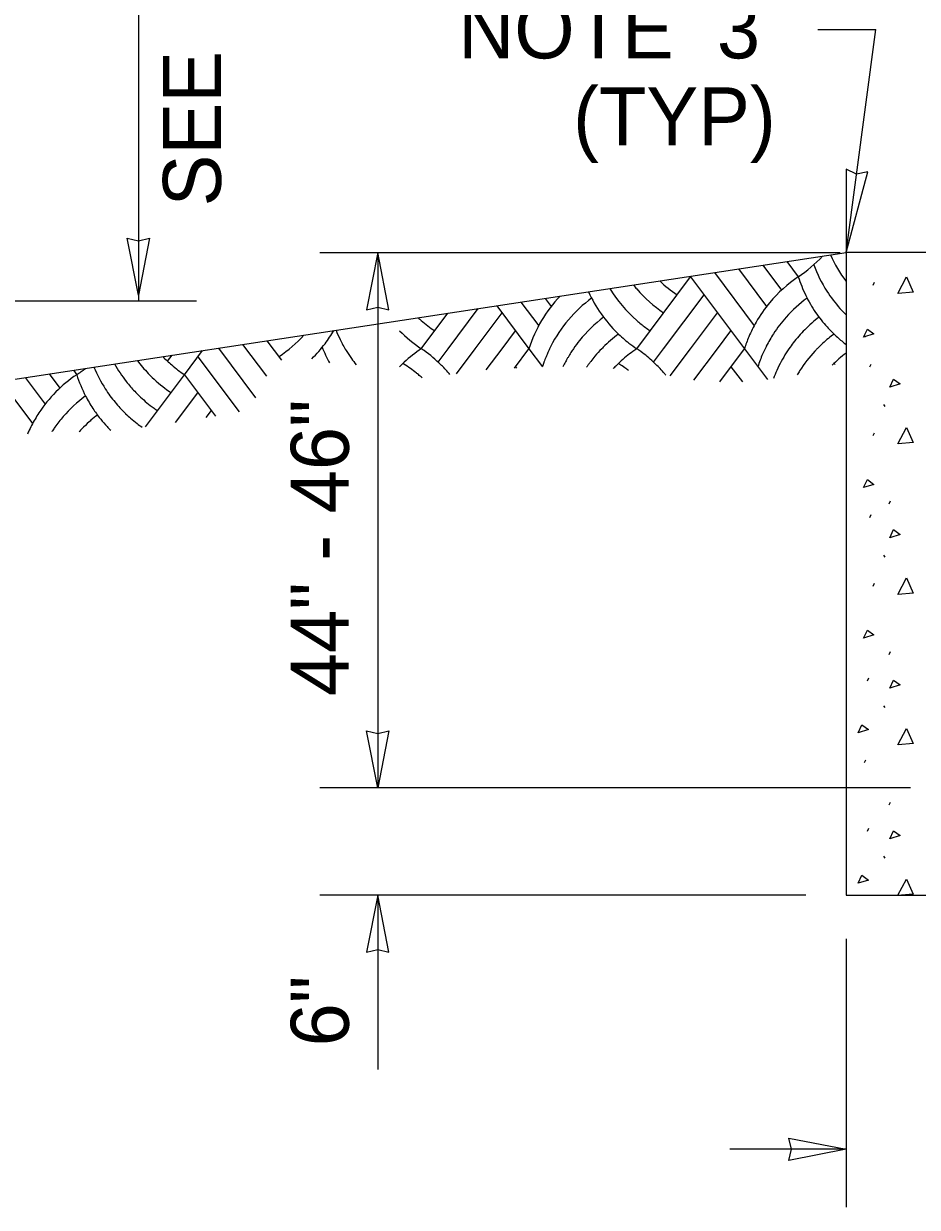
# Model space of a CAD drawing. Extents: x 99862 to 103151, y 99997 to 117076.
# Drawn here: x 101256 to 101502.3, y 109770.1 to 110096.3 of the extents above; entities that cross this region are included whole.
import ezdxf

# ---------------------------------------------------------------- set-up
doc = ezdxf.new("R2010")
doc.units = 0
for name, color, linetype in [('Level 15', 7, 'Continuous'), ('Level 20', 7, 'Continuous'), ('Level 5', 7, 'Continuous'), ('Level 6', 7, 'Continuous')]:
    doc.layers.add(name, color=color, linetype=linetype)

msp = doc.modelspace()

# ---------------------------------------------------------------- linework, layer by layer
at = {"layer": 'Level 15'}
for p, q in [((101287.59, 110394.09), (101287.59, 110019.86)), ((101474.86, 110094.68), (101490.86, 110094.68)), ((101482.66, 110033.17), (101490.86, 110094.68)), ((101353.59, 110033.16), (101353.59, 109885.66)), ((100971.29, 110019.86), (101303.59, 110019.86)), ((101500.42, 109885.66), (101337.59, 109885.66)), ((101471.56, 109856.1), (101337.59, 109856.1)), ((101353.59, 109856.1), (101353.59, 109808.1)), ((101482.66, 109844.1), (101482.66, 109770.1)), ((101482.66, 109786.1), (101450.66, 109786.1))]:
    msp.add_line(p, q, dxfattribs=at)
for points in [[(101482.66, 110033.17), (101488.64, 110055.41), (101485.54, 110054.75), (101482.72, 110056.2)], [(101287.6, 110021.44), (101284.51, 110037.16), (101287.6, 110036.43), (101290.68, 110037.16)], [(101353.59, 110033.16), (101350.5, 110017.44), (101353.59, 110018.17), (101356.67, 110017.44)], [(101353.59, 109885.66), (101350.5, 109901.39), (101353.59, 109900.66), (101356.67, 109901.39)], [(101353.59, 109856.1), (101350.5, 109840.37), (101353.59, 109841.1), (101356.67, 109840.37)], [(101482.66, 109786.1), (101466.93, 109783.01), (101467.66, 109786.1), (101466.93, 109789.18)]]:
    msp.add_lwpolyline(points, close=True, dxfattribs=at)
at = {"layer": 'Level 5'}
for p, q in [((101186.99, 109988.19), (101482.66, 110033.17)), ((101453.02, 110028.66), (101460.77, 110018.33)), ((101459.68, 110029.68), (101464.85, 110022.79)), ((101466.35, 110030.69), (101469.5, 110026.48)), ((101424.95, 110006.68), (101439.8, 110026.48)), ((101439.8, 110026.48), (101439.94, 110026.67)), ((101439.8, 110026.48), (101454.65, 110006.68)), ((101446.35, 110027.65), (101457.33, 110013.02)), ((101432.38, 110006.68), (101443.51, 110021.53)), ((101386.38, 110018.52), (101395.26, 110006.68)), ((101393.04, 110019.54), (101397.93, 110013.02)), ((101399.7, 110020.55), (101401.37, 110018.33)), ((101365.56, 110006.68), (101372.9, 110016.47)), ((101372.98, 110006.68), (101381.28, 110017.75)), ((101380.41, 110006.68), (101387.83, 110016.58)), ((101439.8, 110006.68), (101447.23, 110016.58)), ((101322.98, 110008.88), (101327.02, 110003.5)), ((101387.83, 110006.68), (101391.54, 110011.63)), ((101447.23, 110006.68), (101450.94, 110011.63)), ((101488.05, 110010.06), (101488.07, 110010.08)), ((101300.3, 109999.52), (101305.3, 110006.19)), ((101309.65, 110006.85), (101319.9, 109993.19)), ((101316.32, 110007.87), (101322.87, 109999.13)), ((101370.21, 110002.99), (101372.98, 110006.68)), ((101375.25, 109999.81), (101380.41, 110006.68)), ((101383.45, 110000.84), (101387.83, 110006.68)), ((101391.22, 110001.3), (101395.26, 110006.68)), ((101395.26, 110006.68), (101398.96, 110001.74)), ((101429.61, 110002.99), (101432.38, 110006.68)), ((101434.17, 109999.18), (101439.8, 110006.68)), ((101440.71, 109997.99), (101447.23, 110006.68)), ((101447.84, 109997.6), (101454.65, 110006.68)), ((101454.65, 110006.68), (101460.98, 109998.24)), ((101295.65, 110003.22), (101296.92, 110004.91)), ((101304.01, 110004.47), (101315.38, 109989.32)), ((101256.34, 109998.74), (101261.87, 109991.37)), ((101263.01, 109999.76), (101265.95, 109995.83)), ((101269.67, 110000.77), (101270.6, 109999.52)), ((101289.55, 109985.19), (101300.3, 109999.52)), ((101300.3, 109999.52), (101308.86, 109988.11)), ((101391.54, 110001.73), (101391.84, 110001.34)), ((101450.94, 110001.73), (101454.08, 109997.55)), ((101249.68, 109997.73), (101258.43, 109986.06)), ((101297.82, 109986.32), (101304.01, 109994.57)), ((101306.27, 109987.69), (101307.73, 109989.62))]:
    msp.add_line(p, q, dxfattribs=at)
msp.add_lwpolyline([(101337.59, 110033.16), (101481.02, 110033.16)], dxfattribs=at)
for centre, start, end in [((101448.54, 110057.67), 303.9036, 317.2843), ((101512.73, 110047.77), 203.9439, 216.8537), ((101509.02, 110042.82), 200.2432, 212.6697), ((101457.05, 110052.72), 226.7377, 236.0964), ((101460.76, 110057.67), 235.7238, 236.0964), ((101490.46, 109995.3), 123.9036, 140.1077), ((101505.31, 110037.87), 197.6434, 206.045), ((101445.91, 110037.87), 204.3601, 225.6138), ((101449.63, 110042.82), 211.3642, 228.9599), ((101453.34, 110047.77), 218.7492, 220.9416), ((101453.34, 110047.77), 220.9415, 236.0964), ((101509.02, 110042.82), 212.6697, 221.7589), ((101431.07, 109995.3), 136.4665, 162.3566), ((101434.78, 109990.35), 126.3063, 153.0821), ((101490.46, 109995.3), 140.1077, 150.1544), ((101494.17, 109990.35), 126.3063, 138.2792), ((101505.31, 110037.87), 206.045, 214.3097), ((101390.23, 110042.82), 227.2488, 228.9599), ((101438.49, 109985.4), 127.1006, 141.2057), ((101494.17, 109990.35), 138.2792, 146.9702), ((101497.89, 109985.4), 127.1006, 135.1216), ((101505.31, 110037.87), 214.3097, 222.0851), ((101509.02, 110042.82), 221.7589, 225.4623), ((101309.04, 110030.71), 322.9687, 329.5856), ((101376.95, 110025.76), 201.84, 206.0839), ((101390.23, 110042.82), 228.9599, 236.0964), ((101449.63, 110042.82), 228.9599, 233.6468), ((101449.63, 110042.82), 233.6468, 236.0964), ((101490.46, 109995.3), 150.1544, 157.0116), ((101497.89, 109985.4), 135.1216, 142.4119), ((101505.31, 110037.87), 222.0851, 228.2624), ((101305.33, 110035.66), 304.1564, 317.82), ((101376.95, 110025.76), 206.0839, 211.332), ((101386.52, 110037.87), 224.2383, 236.0964), ((101438.49, 109985.4), 141.2057, 145.4911), ((101442.2, 109980.45), 126.331, 134.9019), ((101445.91, 110037.87), 225.6138, 232.0648), ((101490.46, 109995.3), 157.0116, 162.3566), ((101494.17, 109990.35), 146.9702, 153.0191), ((101501.6, 109980.45), 129.3078, 135.7128), ((101501.6, 109980.45), 126.331, 129.3078), ((101505.31, 110037.87), 228.2624, 232.9445), ((101509.01, 110041.24), 235.3885, 236.0964), ((101309.04, 110030.71), 314.562, 322.9687), ((101373.23, 110020.81), 201.4344, 208.6781), ((101376.95, 110025.76), 211.3319, 215.4021), ((101386.52, 109975.5), 124.9923, 134.2208), ((101386.52, 109975.5), 123.9036, 124.9923), ((101344.6, 109975.5), 54.6602, 56.0963), ((101344.6, 109975.5), 45.3865, 54.6602), ((101434.78, 109990.35), 156.4888, 157.9051), ((101434.78, 109990.35), 154.2265, 156.4888), ((101434.78, 109990.35), 153.0821, 154.2266), ((101438.49, 109985.4), 147.4647, 149.7955), ((101438.49, 109985.4), 145.491, 147.4647), ((101442.2, 109980.45), 135.7127, 139.9547), ((101442.2, 109980.45), 134.9019, 135.7128), ((101445.91, 109975.5), 125.8877, 133.0411), ((101445.91, 110037.87), 232.0648, 236.0964), ((101445.91, 109975.5), 123.9036, 125.8877), ((101403.99, 109975.5), 54.7113, 56.0963), ((101403.99, 109975.5), 48.0975, 54.7113), ((101494.17, 109990.35), 156.7026, 162.3566), ((101494.17, 109990.35), 154.2265, 156.7026), ((101494.17, 109990.35), 153.0191, 154.2266), ((101497.89, 109985.4), 147.511, 155.9945), ((101497.89, 109985.4), 145.491, 147.511), ((101497.89, 109985.4), 142.4119, 145.4911), ((101501.6, 109980.45), 137.0914, 147.6079), ((101501.6, 109980.45), 135.7127, 137.0914), ((101505.31, 109975.5), 127.0555, 134.8743), ((101313.84, 110020.81), 209.1707, 217.9878), ((101317.55, 110025.76), 216.4194, 223.5299), ((101321.26, 110030.71), 224.1905, 229.318), ((101321.26, 110030.71), 229.318, 236.0964), ((101305.33, 110035.66), 303.9036, 304.1564), ((101376.95, 110025.76), 215.4021, 218.645), ((101386.52, 109975.5), 134.2208, 135.7617), ((101340.88, 109970.55), 58.0124, 58.5465), ((101340.88, 109970.55), 51.5475, 58.0124), ((101344.6, 109975.5), 43.7255, 45.3865), ((101434.78, 109990.35), 160.5686, 162.2948), ((101434.78, 109990.35), 160.3753, 160.5686), ((101434.78, 109990.35), 157.9051, 160.3753), ((101438.49, 109985.4), 153.6426, 154.3225), ((101438.49, 109985.4), 153.0508, 153.6426), ((101438.49, 109985.4), 150.9533, 153.0508), ((101438.49, 109985.4), 149.7955, 150.9533), ((101442.2, 109980.45), 144.1103, 145.3356), ((101442.2, 109980.45), 142.8047, 144.1103), ((101442.2, 109980.45), 139.9547, 142.8047), ((101445.91, 109975.5), 135.3485, 136.3375), ((101445.91, 109975.5), 134.5423, 135.3485), ((101445.91, 109975.5), 133.0411, 134.5423), ((101400.28, 109970.55), 57.8664, 58.5465), ((101400.28, 109970.55), 55.3428, 57.8664), ((101403.99, 109975.5), 43.214, 48.0955), ((101403.99, 109975.5), 48.0955, 48.0975), ((101459.68, 109970.55), 57.8948, 58.5465), ((101291.56, 109968.34), 123.9036, 146.6417), ((101249.64, 110030.71), 303.9036, 308.4317), ((101306.41, 110010.91), 197.6434, 207.3584), ((101310.13, 110015.86), 202.2523, 212.6171), ((101317.55, 110025.76), 223.5299, 232.9278), ((101340.88, 109970.55), 51.0705, 51.5475), ((101340.88, 109970.55), 48.9597, 51.0705), ((101340.88, 109970.55), 48.837, 48.9597), ((101340.88, 109970.55), 48.3534, 48.837), ((101344.6, 109975.5), 41.2159, 43.7255), ((101344.6, 109975.5), 40.8111, 41.2159), ((101344.6, 109975.5), 39.8643, 40.8111), ((101434.78, 109990.35), 162.2948, 162.3399), ((101442.2, 109980.45), 145.3356, 145.7985), ((101445.91, 109975.5), 136.3375, 136.9857), ((101400.28, 109970.55), 55.1624, 55.3428), ((101400.28, 109970.55), 53.4219, 55.1624), ((101403.99, 109975.5), 40.215, 43.214), ((101403.99, 109975.5), 39.4904, 40.215), ((101497.89, 109985.4), 155.9945, 159.6031), ((101501.6, 109980.45), 147.6079, 149.5817), ((101310.13, 110015.86), 212.6171, 219.5272), ((101313.84, 110020.81), 217.9878, 220.9416), ((101313.84, 110020.81), 220.9415, 225.9961), ((101317.55, 110025.76), 232.9278, 236.0964), ((101295.28, 109963.39), 126.4475, 139.1485), ((101295.28, 109963.39), 126.3063, 126.4475), ((101306.41, 110010.91), 207.3584, 213.3697), ((101313.84, 110020.81), 225.9961, 233.2498), ((101291.56, 109968.34), 146.6417, 152.7485), ((101306.41, 110010.91), 213.3697, 218.6506), ((101310.13, 110015.86), 219.5272, 225.8263), ((101310.13, 110015.86), 225.8263, 226.1069), ((101313.84, 110020.81), 233.2498, 234.3302), ((101313.84, 110020.81), 234.3302, 236.0964), ((101295.28, 109963.39), 139.1485, 144.7847), ((101298.99, 109958.44), 131.6593, 135.9149), ((101298.99, 109958.44), 130.6246, 131.6593), ((101298.99, 109958.44), 127.1006, 130.6246), ((101306.41, 110010.91), 218.6506, 218.9689), ((101306.41, 110010.91), 218.9689, 223.0435), ((101310.13, 110015.86), 226.1069, 228.9599), ((101310.12, 110015.86), 228.9599, 232.4304), ((101310.12, 110015.86), 232.4304, 235.0437), ((101291.56, 109968.34), 155.9429, 156.8593), ((101291.56, 109968.34), 155.6782, 155.9429), ((101291.56, 109968.34), 152.7485, 155.6782), ((101295.28, 109963.39), 147.0722, 147.1623), ((101295.28, 109963.39), 146.6098, 147.0722), ((101295.28, 109963.39), 144.7847, 146.6098), ((101298.99, 109958.44), 135.9149, 137.5223), ((101306.41, 110010.91), 223.0435, 225.3)]:
    msp.add_arc(centre, 37.58, start, end, dxfattribs=at)
at = {"layer": 'Level 6'}
for p, q in [((101490.11, 110024.23), (101490.46, 110025.03)), ((101489.22, 110001.67), (101489.58, 110002.47)), ((101493.02, 109991.28), (101493.37, 109990.75)), ((101490.11, 109982.75), (101490.46, 109983.54)), ((101494.53, 109963.95), (101494.88, 109964.75)), ((101489.22, 109960.19), (101489.58, 109960.99)), ((101493.02, 109949.8), (101493.37, 109949.27)), ((101490.11, 109941.26), (101490.46, 109942.06)), ((101494.53, 109922.46), (101494.88, 109923.26)), ((101488.6, 109915.21), (101488.96, 109916.01)), ((101493.02, 109908.31), (101493.37, 109907.79)), ((101487.71, 109892.65), (101488.07, 109893.45)), ((101494.53, 109880.98), (101494.88, 109881.78)), ((101488.6, 109873.73), (101488.96, 109874.53)), ((101493.02, 109866.83), (101493.37, 109866.31))]:
    msp.add_line(p, q, dxfattribs=at)
for points in [[(101511.38, 110033.17), (101482.66, 110033.17), (101482.66, 109856.1)], [(101482.66, 109856.1), (101554.66, 109856.1), (101554.66, 110033.17)], [(101496.93, 110021.94), (101499.32, 110026.47), (101501.19, 110022.3), (101497.02, 110021.94)], [(101487.46, 110009.89), (101488.53, 110012.11), (101490.3, 110010.77), (101487.46, 110009.89)], [(101494.71, 109996.1), (101495.77, 109998.32), (101497.55, 109996.99), (101494.71, 109996.1)], [(101496.93, 109980.46), (101499.32, 109984.99), (101501.19, 109980.82), (101497.02, 109980.46)], [(101487.46, 109968.41), (101488.53, 109970.63), (101490.3, 109969.29), (101487.46, 109968.41)], [(101494.71, 109954.62), (101495.77, 109956.84), (101497.55, 109955.51), (101494.71, 109954.62)], [(101496.93, 109938.98), (101499.32, 109943.51), (101501.19, 109939.34), (101497.02, 109938.98)], [(101487.46, 109926.92), (101488.53, 109929.14), (101490.3, 109927.81), (101487.46, 109926.92)], [(101494.71, 109913.14), (101495.77, 109915.36), (101497.55, 109914.03), (101494.71, 109913.14)], [(101485.96, 109900.87), (101487.02, 109903.09), (101488.8, 109901.76), (101485.96, 109900.87)], [(101496.93, 109897.5), (101499.32, 109902.03), (101501.19, 109897.86), (101497.02, 109897.5)], [(101494.71, 109871.66), (101495.77, 109873.88), (101497.55, 109872.55), (101494.71, 109871.66)], [(101485.96, 109859.39), (101487.02, 109861.61), (101488.8, 109860.28), (101485.96, 109859.39)], [(101496.97, 109856.1), (101499.32, 109860.55), (101501.19, 109856.37), (101497.95, 109856.1)]]:
    msp.add_lwpolyline(points, dxfattribs=at)

# ---------------------------------------------------------------- texts
at = {"layer": 'Level 20'}
for s, p in [('NOTE  3', (101375.74, 110086.69)), ('(TYP)', (101407.42, 110062.69))]:
    msp.add_text(s, height=16, dxfattribs=at).set_placement(p)
for s, p in [('SEE ', (101310.36, 110045.9)), ('44" - 46"', (101345.59, 109910.93)), ('6"', (101345.59, 109814.44))]:
    msp.add_text(s, height=16, rotation=90, dxfattribs=at).set_placement(p)

doc.saveas('drawing.dxf')
